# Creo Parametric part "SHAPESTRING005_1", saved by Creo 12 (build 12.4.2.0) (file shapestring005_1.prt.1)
Units: Custom; MM, KILOGRAM, SECS

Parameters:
  PTC_WM_ITERATION = "0"
  PTC_WM_VERSION = "-.0"
  PTC_WM_LIFECYCLE_STATE = "In Work"
  PTC_WM_LIFECYCLE = "MO_CADDocument"
  PTC_WM_CREATED_BY = "Maximilian Roepper (Z0017RMS: MO)"
  PTC_WM_CREATED_ON = "18-Sep-26 11:36:42 AM"
  PTC_WM_MODIFIED_BY = "Maximilian Roepper (Z0017RMS: MO)"
  PTC_WM_MODIFIED_ON = "18-Sep-26 11:36:46 AM"
  PDMLINKNUMBER = "PDM000071455332"
  PTC_WM_NAME = "shapestring005_1.prt"
  PTC_WM_NUMBER = "PDM000071455332"

Other parameters: WEIGHT, WEIGHT_FACTOR, WEIGHT_ADD, _MASS_TEMP, _DIFF_TEMP, MC_ERRORS, SUPPLIER

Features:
  1. coordinate system
  2. datum plane "PRT_YZ"
  3. datum plane "PRT_XY"
  4. datum plane "PRT_XZ"
  5. coordinate system
  6. datum axis
  7. datum axis
  8. datum axis
  9. coordinate system
  10. imported feature
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
Other named items: PRT, SIEMENS_MO, DRW_VIEW_ORG, PRT_X, PRT_Y, PRT_Z, CS0, ROUGH_GROB

Layers: 00_STD_CSYS-KSYS, 01_STD_PLANES-EBENEN, 02_STD_AXES-ACHSEN, 03_STD_CSYS-KSYS, 24_IMPORT_FEAT-IMPORT_KE, WHITE

Surfaces: 1 plane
